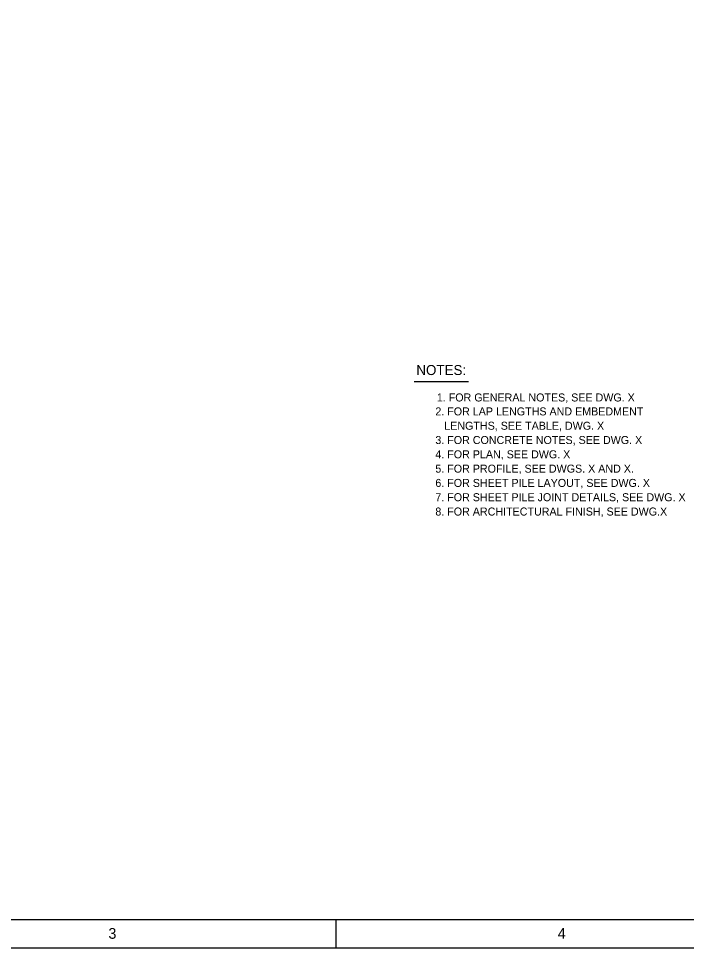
# Model space of a CAD drawing. Extents: x 22369.6 to 22428.3, y 22369.6 to 22415.
# Drawn here: x 22395.6 to 22411.18, y 22369.62 to 22391.29 of the extents above; entities that cross this region are included whole.
import ezdxf

# ---------------------------------------------------------------- set-up
doc = ezdxf.new("R2010")
doc.units = 0
for name, color, linetype in [('Level 1', 7, 'Continuous'), ('Level 10', 7, 'Continuous'), ('Level 4', 7, 'Continuous'), ('Level 7', 7, 'Continuous'), ('Level 9', 7, 'Continuous')]:
    doc.layers.add(name, color=color, linetype=linetype)

msp = doc.modelspace()

# ---------------------------------------------------------------- linework, layer by layer
at = {"layer": 'Level 1'}
msp.add_lwpolyline([(22369.621, 22414.955), (22428.288, 22414.955), (22428.288, 22369.621), (22369.621, 22369.621)], close=True, dxfattribs=at)
at = {"layer": 'Level 10'}
msp.add_line((22403.008, 22369.616), (22403.008, 22370.288), dxfattribs=at)
at = {"layer": 'Level 7'}
msp.add_line((22404.828, 22382.828), (22406.093, 22382.828), dxfattribs=at)
at = {"layer": 'Level 9'}
msp.add_line((22371.621, 22370.288), (22423.952, 22370.288), dxfattribs=at)

# ---------------------------------------------------------------- texts
at = {"layer": 'Level 1'}
for s, p in [('3', (22397.696, 22369.84)), ('4', (22408.176, 22369.84))]:
    msp.add_text(s, height=0.25, dxfattribs=at).set_placement(p)
at = {"layer": 'Level 4'}
for s, p in [('1. FOR GENERAL NOTES, SEE DWG. X', (22405.356, 22382.364)), ('2. FOR LAP LENGTHS AND EMBEDMENT', (22405.321, 22382.039)), ('   LENGTHS, SEE TABLE, DWG. X', (22405.321, 22381.705)), ('3. FOR CONCRETE NOTES, SEE DWG. X', (22405.321, 22381.372)), ('4. FOR PLAN, SEE DWG. X', (22405.321, 22381.039)), ('5. FOR PROFILE, SEE DWGS. X AND X.', (22405.321, 22380.705)), ('6. FOR SHEET PILE LAYOUT, SEE DWG. X', (22405.321, 22380.372)), ('7. FOR SHEET PILE JOINT DETAILS, SEE DWG. X', (22405.321, 22380.039)), ('8. FOR ARCHITECTURAL FINISH, SEE DWG.X', (22405.321, 22379.705))]:
    msp.add_text(s, height=0.18659, dxfattribs=at).set_placement(p)
at = {"layer": 'Level 7'}
msp.add_text('NOTES:', height=0.2332, dxfattribs=at).set_placement((22404.878, 22382.98))

doc.saveas('drawing.dxf')
